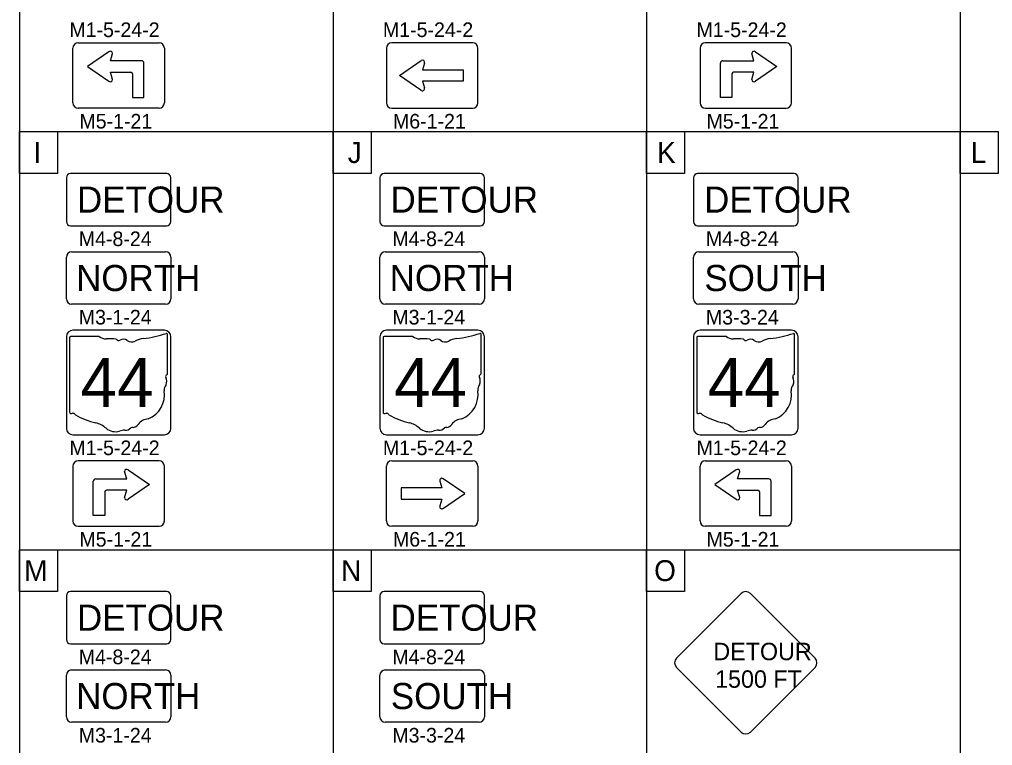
# Model space of a CAD drawing. Extents: x 0 to 34, y 0 to 22.
# Drawn here: x 19.7 to 29.01, y 7.41 to 14.36 of the extents above; entities that cross this region are included whole.
import ezdxf

# ---------------------------------------------------------------- set-up
doc = ezdxf.new("R2010")
doc.units = 0
for name, color, linetype in [('SC_Scratch1', 7, 'Continuous'), ('SH_Text', 7, 'Continuous'), ('SN_P_Signs', 7, 'Continuous'), ('SN_P_Text', 7, 'Continuous')]:
    doc.layers.add(name, color=color, linetype=linetype)

msp = doc.modelspace()

# ---------------------------------------------------------------- linework, layer by layer
at = {"layer": 'SC_Scratch1'}
for p, q in [((19.7007, 21.2819), (19.7007, 3.1937)), ((22.7007, 21.2819), (22.7007, 3.1937)), ((25.7007, 21.2819), (25.7007, 3.1937)), ((28.7007, 21.2819), (28.7007, 3.1937)), ((19.7007, 13.2819), (28.7007, 13.2819)), ((19.7007, 9.2819), (28.7007, 9.2819))]:
    msp.add_line(p, q, dxfattribs=at)
at = {"layer": 'SH_Text'}
for points in [[(19.7007, 13.2819), (20.0642, 13.2819), (20.0642, 12.8819), (19.7007, 12.8819)], [(22.7007, 13.2819), (23.0642, 13.2819), (23.0642, 12.8819), (22.7007, 12.8819)], [(25.7007, 13.2819), (26.0642, 13.2819), (26.0642, 12.8819), (25.7007, 12.8819)], [(28.7007, 13.2819), (29.0642, 13.2819), (29.0642, 12.8819), (28.7007, 12.8819)], [(19.7007, 9.2819), (20.0642, 9.2819), (20.0642, 8.8819), (19.7007, 8.8819)], [(22.7007, 9.2819), (23.0642, 9.2819), (23.0642, 8.8819), (22.7007, 8.8819)], [(25.7007, 9.2819), (26.0642, 9.2819), (26.0642, 8.8819), (25.7007, 8.8819)]]:
    msp.add_lwpolyline(points, close=True, dxfattribs=at)
at = {"layer": 'SN_P_Signs'}
for p, q in [((20.2118, 13.5568), (20.2118, 14.0818)), ((20.2618, 14.1318), (21.0368, 14.1318)), ((21.0868, 14.0818), (21.0868, 13.5568)), ((23.2118, 14.0818), (23.2118, 13.5568)), ((24.0368, 14.1318), (23.2618, 14.1318)), ((24.0369, 14.1318), (24.0368, 14.1318)), ((24.0868, 13.5568), (24.0868, 14.0818)), ((26.2118, 14.0818), (26.2118, 13.5568)), ((27.0368, 14.1318), (26.2618, 14.1318)), ((27.0868, 13.5568), (27.0868, 14.0818)), ((20.5565, 14.045), (20.3525, 13.9053)), ((20.5712, 13.9599), (20.5921, 14.0303)), ((26.7274, 13.9599), (26.7066, 14.0303)), ((26.7421, 14.045), (26.9461, 13.9053)), ((20.3525, 13.9053), (20.5565, 13.7655)), ((20.8681, 13.9599), (20.5712, 13.9599)), ((20.8681, 13.9599), (20.8681, 13.9599)), ((20.8916, 13.6083), (20.8916, 13.9365)), ((23.3368, 13.8193), (23.5437, 13.9615)), ((23.5755, 13.9382), (23.5556, 13.874)), ((23.5556, 13.874), (23.9461, 13.874)), ((23.9461, 13.874), (23.9461, 13.7646)), ((26.4071, 13.6083), (26.4071, 13.9365)), ((26.4305, 13.9599), (26.7274, 13.9599)), ((26.4305, 13.9599), (26.4305, 13.9599)), ((26.9461, 13.9053), (26.7421, 13.7655)), ((20.5921, 13.7803), (20.5712, 13.8505)), ((20.5712, 13.8505), (20.7666, 13.8505)), ((20.7821, 13.8349), (20.7821, 13.6083)), ((23.5408, 13.6796), (23.3368, 13.8193)), ((26.5165, 13.8349), (26.5165, 13.6083)), ((26.7274, 13.8505), (26.5321, 13.8505)), ((26.7066, 13.7803), (26.7274, 13.8505)), ((23.9461, 13.7646), (23.5556, 13.7646)), ((23.5556, 13.7646), (23.5755, 13.7005)), ((20.7821, 13.6083), (20.8916, 13.6083)), ((20.7821, 13.6083), (20.8916, 13.6083)), ((26.5165, 13.6083), (26.4071, 13.6083)), ((21.0368, 13.5068), (20.2618, 13.5068)), ((23.2618, 13.5068), (24.0368, 13.5068)), ((26.2618, 13.5068), (27.0368, 13.5068)), ((20.1993, 12.1319), (21.0993, 12.1319)), ((23.1993, 12.1319), (24.0993, 12.1319)), ((26.1993, 12.1318), (27.0993, 12.1318)), ((20.1493, 11.6819), (20.1493, 12.0819)), ((21.1493, 12.0819), (21.1493, 11.6819)), ((23.1493, 11.6819), (23.1493, 12.0819)), ((24.1493, 12.0819), (24.1493, 11.6819)), ((26.1493, 11.6818), (26.1493, 12.0818)), ((27.1493, 12.0818), (27.1493, 11.6818)), ((21.0993, 11.6319), (20.1993, 11.6319)), ((24.0993, 11.6319), (23.1993, 11.6319)), ((27.0993, 11.6318), (26.1993, 11.6318)), ((20.1799, 11.3098), (20.1799, 10.5982)), ((20.4636, 11.322), (20.1891, 11.322)), ((21.1173, 10.9674), (21.1173, 11.3397)), ((23.1799, 11.3098), (23.1799, 10.5982)), ((23.4636, 11.322), (23.1891, 11.322)), ((24.1173, 10.9674), (24.1173, 11.3397)), ((26.1799, 11.3098), (26.1799, 10.5982)), ((26.4636, 11.322), (26.1891, 11.322)), ((27.1173, 10.9674), (27.1173, 11.3397)), ((21.1172, 10.9675), (21.1173, 10.9674)), ((24.1172, 10.9675), (24.1173, 10.9674)), ((27.1172, 10.9675), (27.1173, 10.9674)), ((20.2118, 10.0818), (20.2118, 9.5568)), ((21.0368, 10.1318), (20.2618, 10.1318)), ((21.0868, 9.5568), (21.0868, 10.0818)), ((23.2118, 9.5568), (23.2118, 10.0818)), ((23.2618, 10.1318), (24.0368, 10.1318)), ((24.0868, 10.0818), (24.0868, 9.5568)), ((26.2118, 9.5568), (26.2118, 10.0818)), ((26.2618, 10.1318), (27.0368, 10.1318)), ((27.0868, 10.0818), (27.0868, 9.5568)), ((20.7274, 9.9599), (20.7066, 10.0303)), ((20.7421, 10.045), (20.9461, 9.9053)), ((26.5565, 10.045), (26.3525, 9.9053)), ((26.5712, 9.9599), (26.5921, 10.0303)), ((20.4071, 9.6083), (20.4071, 9.9365)), ((20.4305, 9.9599), (20.7274, 9.9599)), ((20.4305, 9.9599), (20.4305, 9.9599)), ((20.9461, 9.9053), (20.7421, 9.7655)), ((23.7431, 9.874), (23.3525, 9.874)), ((23.3525, 9.874), (23.3525, 9.7646)), ((23.7231, 9.9382), (23.7431, 9.874)), ((23.9618, 9.8193), (23.7549, 9.9615)), ((26.3525, 9.9053), (26.5565, 9.7655)), ((26.8681, 9.9599), (26.5712, 9.9599)), ((26.8681, 9.9599), (26.8681, 9.9599)), ((26.8916, 9.6083), (26.8916, 9.9365)), ((20.5165, 9.8349), (20.5165, 9.6083)), ((20.7274, 9.8505), (20.5321, 9.8505)), ((20.7066, 9.7803), (20.7274, 9.8505)), ((23.7578, 9.6796), (23.9618, 9.8193)), ((26.5921, 9.7803), (26.5712, 9.8505)), ((26.5712, 9.8505), (26.7666, 9.8505)), ((26.7821, 9.8349), (26.7821, 9.6083)), ((23.3525, 9.7646), (23.7431, 9.7646)), ((23.7431, 9.7646), (23.7231, 9.7005)), ((20.5165, 9.6083), (20.4071, 9.6083)), ((26.7821, 9.6083), (26.8916, 9.6083)), ((26.7821, 9.6083), (26.8916, 9.6083)), ((20.2618, 9.5068), (21.0368, 9.5068)), ((24.0368, 9.5068), (23.2618, 9.5068)), ((27.0368, 9.5068), (26.2618, 9.5068)), ((20.1993, 8.1319), (21.0993, 8.1319)), ((23.1993, 8.1318), (24.0993, 8.1318)), ((20.1493, 7.6819), (20.1493, 8.0819)), ((21.1493, 8.0819), (21.1493, 7.6819)), ((23.1493, 7.6818), (23.1493, 8.0818)), ((24.1493, 8.0818), (24.1493, 7.6818)), ((21.0993, 7.6319), (20.1993, 7.6319)), ((24.0993, 7.6318), (23.1993, 7.6318))]:
    msp.add_line(p, q, dxfattribs=at)
for points in [[(21.1093, 12.8819), (20.1893, 12.8819)], [(24.1093, 12.8819), (23.1893, 12.8819)], [(27.1093, 12.8819), (26.1893, 12.8819)], [(20.1493, 12.8419), (20.1493, 12.4219)], [(21.1493, 12.4219), (21.1493, 12.8419)], [(23.1493, 12.8419), (23.1493, 12.4219)], [(24.1493, 12.4219), (24.1493, 12.8419)], [(26.1493, 12.8419), (26.1493, 12.4219)], [(27.1493, 12.4219), (27.1493, 12.8419)], [(20.1893, 12.3819), (21.1093, 12.3819)], [(23.1893, 12.3819), (24.1093, 12.3819)], [(26.1893, 12.3819), (27.1093, 12.3819)], [(21.0868, 11.3819), (20.2118, 11.3819)], [(24.0868, 11.3819), (23.2118, 11.3819)], [(27.0868, 11.3819), (26.2118, 11.3819)], [(20.1493, 11.3194), (20.1493, 10.4443)], [(21.1493, 10.4443), (21.1493, 11.3194)], [(23.1493, 11.3194), (23.1493, 10.4443)], [(24.1493, 10.4443), (24.1493, 11.3194)], [(26.1493, 11.3194), (26.1493, 10.4443)], [(27.1493, 10.4443), (27.1493, 11.3194)], [(20.2118, 10.3818), (21.0868, 10.3818)], [(23.2118, 10.3818), (24.0868, 10.3818)], [(26.2118, 10.3818), (27.0868, 10.3818)], [(21.1093, 8.8819), (20.1893, 8.8819)], [(24.1093, 8.8819), (23.1893, 8.8819)], [(25.9864, 8.2448), (26.6051, 8.8635)], [(26.6935, 8.8635), (27.3122, 8.2448)], [(20.1493, 8.8419), (20.1493, 8.4219)], [(21.1493, 8.4219), (21.1493, 8.8419)], [(23.1493, 8.8419), (23.1493, 8.4219)], [(24.1493, 8.4219), (24.1493, 8.8419)], [(20.1893, 8.3819), (21.1093, 8.3819)], [(23.1893, 8.3819), (24.1093, 8.3819)], [(26.6051, 7.5377), (25.9864, 8.1564)], [(27.3122, 8.1564), (26.6935, 7.5377)]]:
    msp.add_lwpolyline(points, dxfattribs=at)
for centre, radius, start, end in [((20.2618, 14.0819), 0.05, 90, 180), ((21.0368, 14.0819), 0.05, 0, 90), ((23.2619, 14.0819), 0.05, 90, 180), ((24.0369, 14.0819), 0.05, 0, 90), ((26.2618, 14.0818), 0.05, 90, 180), ((27.0368, 14.0818), 0.05, 0, 90), ((20.5712, 14.0303), 0.0209, 0.00165, 134.99986), ((23.5556, 13.9444), 0.0209, 342.79539, 124.58878), ((26.7274, 14.0303), 0.0209, 45.00014, 179.99835), ((20.8681, 13.9365), 0.0235, 0, 90), ((26.4305, 13.9365), 0.0235, 90, 180), ((20.5712, 13.7803), 0.0209, 225.00014, 0.00165), ((20.7665, 13.8349), 0.0156, 0, 90), ((26.5321, 13.8349), 0.0156, 90, 180), ((26.7274, 13.7803), 0.0209, 179.99835, 314.99986), ((23.5556, 13.6944), 0.0209, 224.99044, 17.20461), ((20.2618, 13.5569), 0.05, 180, 270), ((21.0368, 13.5569), 0.05, 270, 360), ((23.2619, 13.5569), 0.05, 180, 270), ((24.0369, 13.5569), 0.05, 270, 0), ((26.2618, 13.5568), 0.05, 180, 270), ((27.0368, 13.5568), 0.05, 270, 0), ((20.1893, 12.8419), 0.04, 90, 180), ((21.1093, 12.8419), 0.04, 0, 90), ((23.1893, 12.8419), 0.04, 90, 180), ((24.1093, 12.8419), 0.04, 0, 90), ((26.1893, 12.8419), 0.04, 90, 180), ((27.1093, 12.8419), 0.04, 0, 90), ((20.1893, 12.4219), 0.04, 180, 270), ((21.1093, 12.4219), 0.04, 270, 0), ((23.1893, 12.4219), 0.04, 180, 270), ((24.1093, 12.4219), 0.04, 270, 0), ((26.1893, 12.4219), 0.04, 180, 270), ((27.1093, 12.4219), 0.04, 270, 0), ((20.1993, 12.0818), 0.05, 90, 180), ((21.0993, 12.0818), 0.05, 0, 90), ((23.1993, 12.0818), 0.05, 90, 180), ((24.0993, 12.0818), 0.05, 0, 90), ((26.1993, 12.0818), 0.05, 90, 180), ((27.0993, 12.0818), 0.05, 0, 90), ((20.1993, 11.6818), 0.05, 180, 270), ((21.0993, 11.6818), 0.05, 270, 0), ((23.1993, 11.6818), 0.05, 180, 270), ((24.0993, 11.6818), 0.05, 270, 0), ((26.1993, 11.6818), 0.05, 180, 270), ((27.0993, 11.6818), 0.05, 270, 0), ((20.2118, 11.3194), 0.0625, 90, 180), ((21.0868, 11.3194), 0.0625, 0, 90), ((23.2118, 11.3194), 0.0625, 90, 180), ((24.0868, 11.3194), 0.0625, 0, 90), ((26.2118, 11.3194), 0.0625, 90, 180), ((27.0868, 11.3194), 0.0625, 0, 90), ((20.1906, 11.3113), 0.0109, 98.1301, 188.1301), ((20.529, 11.4046), 0.1053, 231.61951, 271.11188), ((20.5639, 10.9226), 0.3782, 80.48669, 94.98827), ((20.6498, 11.315), 0.0304, 219.79206, 297.10237), ((20.6944, 11.2328), 0.0632, 54.46668, 119.14113), ((20.776, 11.3455), 0.076, 233.85621, 294.82819), ((20.9102, 11.1047), 0.2, 97.34618, 120.76885), ((20.7834, 12.2921), 0.9942, 275.84447, 288.90645), ((21.1069, 11.3412), 0.0104, 351.86209, 97.738), ((23.1906, 11.3113), 0.0109, 98.1301, 188.1301), ((23.529, 11.4046), 0.1053, 231.61951, 271.11188), ((23.5639, 10.9226), 0.3782, 80.48669, 94.98827), ((23.6498, 11.315), 0.0304, 219.79206, 297.10237), ((23.6944, 11.2328), 0.0632, 54.46668, 119.14113), ((23.776, 11.3455), 0.076, 233.85621, 294.82819), ((23.9102, 11.1047), 0.2, 97.34618, 120.76885), ((23.7834, 12.2921), 0.9942, 275.84447, 288.90645), ((24.1069, 11.3412), 0.0104, 351.86209, 97.738), ((26.1906, 11.3113), 0.0109, 98.1301, 188.1301), ((26.529, 11.4046), 0.1053, 231.61951, 271.11188), ((26.5639, 10.9226), 0.3782, 80.48669, 94.98827), ((26.6498, 11.315), 0.0304, 219.79206, 297.10237), ((26.6944, 11.2328), 0.0632, 54.46668, 119.14113), ((26.776, 11.3455), 0.076, 233.85621, 294.82819), ((26.9102, 11.1047), 0.2, 97.34618, 120.76885), ((26.7834, 12.2921), 0.9942, 275.84447, 288.90645), ((27.1069, 11.3412), 0.0104, 351.86209, 97.738), ((21.1149, 10.9401), 0.0162, 107.94398, 210.33697), ((21.0122, 10.8931), 0.097, 340.03296, 23.64957), ((21.1062, 10.966), 0.0112, 289.60381, 7.73413), ((24.1149, 10.9401), 0.0162, 107.94398, 210.33697), ((24.0122, 10.8931), 0.097, 340.03296, 23.64957), ((24.1062, 10.966), 0.0112, 289.60381, 7.73413), ((27.1149, 10.9401), 0.0162, 107.94398, 210.33697), ((27.0122, 10.8931), 0.097, 340.03296, 23.64957), ((27.1062, 10.966), 0.0112, 289.60381, 7.73413), ((20.8391, 10.7643), 0.2487, 292.30889, 8.98584), ((21.1547, 10.8117), 0.0705, 136.8065, 186.92959), ((23.8391, 10.7643), 0.2487, 292.30889, 8.98584), ((24.1547, 10.8117), 0.0705, 136.8065, 186.92959), ((26.8391, 10.7643), 0.2487, 292.30889, 8.98584), ((27.1547, 10.8117), 0.0705, 136.8065, 186.92959), ((20.1907, 10.5967), 0.011, 171.95839, 258.30661), ((20.1924, 10.6695), 0.0836, 267.33899, 280.60386), ((20.2095, 10.5572), 0.0302, 29.74838, 93.27175), ((20.5901, 11.1965), 0.7179, 240.41292, 257.1985), ((20.9439, 10.3985), 0.1362, 94.40312, 142.57675), ((23.1907, 10.5967), 0.011, 171.95839, 258.30661), ((23.1924, 10.6695), 0.0836, 267.33899, 280.60386), ((23.2095, 10.5572), 0.0302, 29.74838, 93.27175), ((23.5901, 11.1965), 0.7179, 240.41292, 257.1985), ((23.9439, 10.3985), 0.1362, 94.40312, 142.57675), ((26.1907, 10.5967), 0.011, 171.95839, 258.30661), ((26.1924, 10.6695), 0.0836, 267.33899, 280.60386), ((26.2095, 10.5572), 0.0302, 29.74838, 93.27175), ((26.5901, 11.1965), 0.7179, 240.41292, 257.1985), ((26.9439, 10.3985), 0.1362, 94.40312, 142.57675), ((20.2118, 10.4443), 0.0625, 180, 270), ((20.3761, 10.2786), 0.2246, 47.18416, 75.83597), ((20.619, 10.5537), 0.1425, 230.70037, 286.29184), ((20.7118, 10.5004), 0.0759, 268.77702, 315.54927), ((20.7805, 10.4315), 0.0214, 65.75173, 132.64842), ((20.7714, 10.5293), 0.0803, 282.87319, 323.27711), ((21.0868, 10.4443), 0.0625, 270, 0), ((23.2118, 10.4443), 0.0625, 180, 270), ((23.3761, 10.2786), 0.2246, 47.18416, 75.83597), ((23.619, 10.5537), 0.1425, 230.70037, 286.29184), ((23.7118, 10.5004), 0.0759, 268.77702, 315.54927), ((23.7805, 10.4315), 0.0214, 65.75173, 132.64842), ((23.7714, 10.5293), 0.0803, 282.87319, 323.27711), ((24.0868, 10.4443), 0.0625, 270, 0), ((26.2118, 10.4443), 0.0625, 180, 270), ((26.3761, 10.2786), 0.2246, 47.18416, 75.83597), ((26.619, 10.5537), 0.1425, 230.70037, 286.29184), ((26.7118, 10.5004), 0.0759, 268.77702, 315.54927), ((26.7805, 10.4315), 0.0214, 65.75173, 132.64842), ((26.7714, 10.5293), 0.0803, 282.87319, 323.27711), ((27.0868, 10.4443), 0.0625, 270, 0), ((20.7014, 10.3077), 0.1171, 85.69512, 111.20995), ((23.7014, 10.3077), 0.1171, 85.69512, 111.20995), ((26.7014, 10.3077), 0.1171, 85.69512, 111.20995), ((20.2618, 10.0818), 0.05, 90, 180), ((21.0368, 10.0818), 0.05, 0, 90), ((23.2618, 10.0819), 0.05, 90, 180), ((24.0368, 10.0819), 0.05, 0, 90), ((26.2618, 10.0819), 0.05, 90, 180), ((27.0368, 10.0819), 0.05, 0, 90), ((20.7274, 10.0303), 0.0209, 45.00014, 179.99835), ((23.7431, 9.9444), 0.0209, 55.41122, 197.20461), ((26.5712, 10.0303), 0.0209, 0.00165, 134.99986), ((20.4305, 9.9365), 0.0235, 90, 180), ((26.8681, 9.9365), 0.0235, 0, 90), ((20.5321, 9.8349), 0.0156, 90, 180), ((20.7274, 9.7803), 0.0209, 179.99835, 314.99986), ((26.5712, 9.7803), 0.0209, 225.00014, 0.00165), ((26.7665, 9.8349), 0.0156, 0, 90), ((23.7431, 9.6944), 0.0209, 162.79539, 315.00956), ((20.2618, 9.5568), 0.05, 180, 270), ((21.0368, 9.5568), 0.05, 270, 0), ((23.2618, 9.5569), 0.05, 180, 270), ((24.0368, 9.5569), 0.05, 270, 360), ((26.2618, 9.5569), 0.05, 180, 270), ((27.0368, 9.5569), 0.05, 270, 360), ((20.1893, 8.8419), 0.04, 90, 180), ((21.1093, 8.8419), 0.04, 0, 90), ((23.1893, 8.8419), 0.04, 90, 180), ((24.1093, 8.8419), 0.04, 0, 90), ((26.6493, 8.8194), 0.0625, 45, 135), ((20.1893, 8.4219), 0.04, 180, 270), ((21.1093, 8.4219), 0.04, 270, 0), ((23.1893, 8.4219), 0.04, 180, 270), ((24.1093, 8.4219), 0.04, 270, 0), ((26.0306, 8.2006), 0.0625, 135, 225), ((27.268, 8.2006), 0.0625, 315, 45), ((20.1993, 8.0818), 0.05, 90, 180), ((21.0993, 8.0818), 0.05, 0, 90), ((23.1993, 8.0818), 0.05, 90, 180), ((24.0993, 8.0818), 0.05, 0, 90), ((20.1993, 7.6818), 0.05, 180, 270), ((21.0993, 7.6818), 0.05, 270, 0), ((23.1993, 7.6818), 0.05, 180, 270), ((24.0993, 7.6818), 0.05, 270, 0), ((26.6493, 7.5819), 0.0625, 225, 315)]:
    msp.add_arc(centre, radius, start, end, dxfattribs=at)

# ---------------------------------------------------------------- texts
at = {"layer": 'SH_Text'}
for s, p in [('I', (19.8357, 12.9819)), ('J', (22.8415, 12.9819)), ('K', (25.8007, 12.9819)), ('L', (28.8007, 12.9819)), ('M', (19.746, 8.9819)), ('N', (22.778, 8.9819)), ('O', (25.773, 8.9819))]:
    msp.add_text(s, height=0.2, dxfattribs=at).set_placement(p)
at = {"layer": 'SN_P_Signs'}
for s, height, p in [('DETOUR', 0.25, (20.2509, 12.5069)), ('DETOUR', 0.25, (23.2509, 12.5069)), ('DETOUR', 0.25, (26.2509, 12.5069)), ('NORTH', 0.25, (20.2427, 11.7568)), ('NORTH', 0.25, (23.2427, 11.7568)), ('SOUTH', 0.25, (26.2537, 11.7568)), ('44', 0.46875, (20.2858, 10.6484)), ('44', 0.46875, (23.2858, 10.6484)), ('44', 0.46875, (26.2858, 10.6484)), ('DETOUR', 0.25, (20.2509, 8.5069)), ('DETOUR', 0.25, (23.2509, 8.5069)), ('DETOUR', 0.16667, (26.3394, 8.2249)), ('1500 FT', 0.16667, (26.356, 7.9611)), ('NORTH', 0.25, (20.2427, 7.7568)), ('SOUTH', 0.25, (23.2537, 7.7568))]:
    msp.add_text(s, height=height, dxfattribs=at).set_placement(p)
at = {"layer": 'SN_P_Text'}
for s, p in [('M1-5-24-2', (20.1779, 14.1868)), ('M1-5-24-2', (23.1779, 14.1868)), ('M1-5-24-2', (26.1779, 14.1868)), ('M5-1-21', (20.274, 13.3118)), ('M6-1-21', (23.274, 13.3118)), ('M5-1-21', (26.274, 13.3118)), ('M4-8-24', (20.268, 12.1869)), ('M4-8-24', (23.268, 12.1869)), ('M4-8-24', (26.268, 12.1869)), ('M3-1-24', (20.268, 11.4369)), ('M3-1-24', (23.268, 11.4369)), ('M3-3-24', (26.268, 11.4368)), ('M1-5-24-2', (20.1779, 10.1868)), ('M1-5-24-2', (23.1779, 10.1868)), ('M1-5-24-2', (26.1779, 10.1868)), ('M5-1-21', (20.274, 9.3118)), ('M6-1-21', (23.274, 9.3118)), ('M5-1-21', (26.274, 9.3118)), ('M4-8-24', (20.268, 8.1869)), ('M4-8-24', (23.268, 8.1869)), ('M3-1-24', (20.268, 7.4369)), ('M3-3-24', (23.268, 7.4368))]:
    msp.add_text(s, height=0.14, dxfattribs=at).set_placement(p)

doc.saveas('drawing.dxf')
